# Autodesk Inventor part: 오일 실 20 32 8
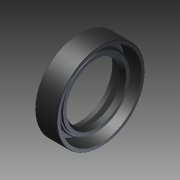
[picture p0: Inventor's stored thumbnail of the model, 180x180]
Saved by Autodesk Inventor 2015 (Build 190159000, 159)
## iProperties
Created: 2024-12
Part Number: 오일 실 20 32 8
Material: 일반
Document SubType Name: Modeling
Designer: 102566
Density: 1 g/cm^3
Appearance: 기본값
Author: 102566
Author: jhkim
Description: 오일-실
Creation Date: 2024-11-28
Sending System: Autodesk Inventor 2025
Preprocessor: ST-DEVELOPER v20
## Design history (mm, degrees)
node "오일 실 20 32 81"
body "Solid1"
node "기준1"
